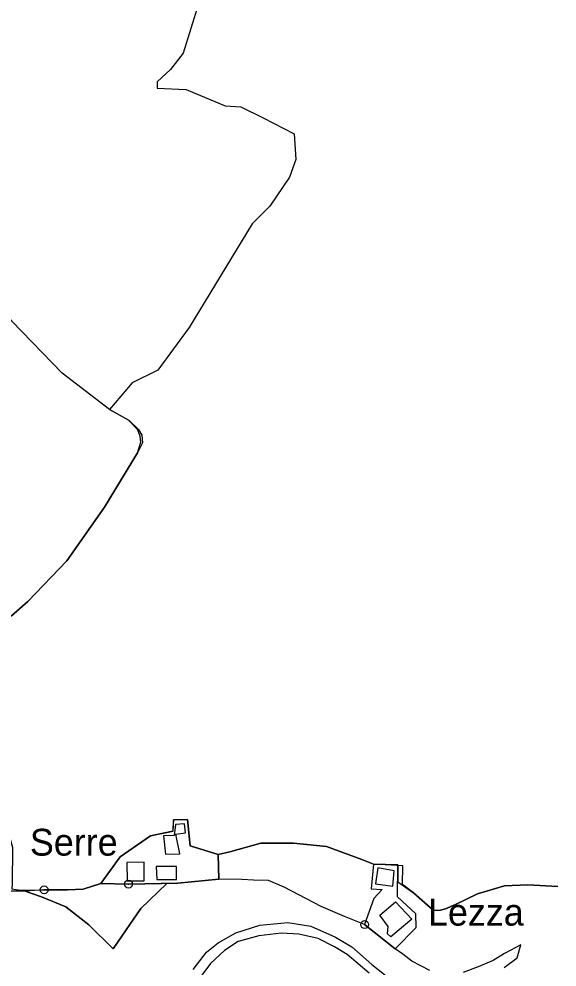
# Model space of a CAD drawing. Extents: x 645880 to 658994, y 884400 to 894744.
# Drawn here: x 656182 to 656523, y 891532 to 892132 of the extents above; entities that cross this region are included whole.
import ezdxf
from ezdxf.enums import TextEntityAlignment as Align

# ---------------------------------------------------------------- set-up
doc = ezdxf.new("R2010")
doc.units = 0
doc.header["$LTSCALE"] = 10
doc.header["$PDMODE"] = 32
doc.header["$PDSIZE"] = 5
for name, color, linetype, lineweight in [('16', 7, 'Continuous', 25), ('17', 7, 'Continuous', 25), ('18', 7, 'Continuous', 25), ('2', 7, 'Continuous', 25), ('55', 7, 'Continuous', 25)]:
    doc.layers.add(name, color=color, linetype=linetype, lineweight=lineweight)
doc.layers.add('60', color=7, linetype='Continuous')

msp = doc.modelspace()

# ---------------------------------------------------------------- linework, layer by layer
at = {"layer": '16'}
for points in [[(656342.45, 892161.69), (656338.47, 892159.67), (656332.55, 892160.05), (656325.48, 892161.2), (656314.98, 892164.64), (656305.18, 892167.58), (656295.98, 892141.92), (656286.31, 892110.77), (656278.25, 892100.48)], [(656278.25, 892100.48), (656269.75, 892092.5), (656269.93, 892088.54), (656288.2, 892087.79)], [(656288.2, 892087.79), (656312.86, 892077.43), (656322.84, 892076.67), (656336.96, 892069.7), (656356.54, 892059.72), (656357.68, 892043.32), (656353.74, 892032.14), (656341.25, 892013.72), (656330.08, 892002.53), (656290.11, 891936.91), (656270.32, 891909.76), (656254.02, 891901.9), (656239.58, 891884.9)], [(656239.58, 891884.9), (656251.8, 891878.19), (656258.02, 891872.19), (656260.02, 891868.63), (656260.47, 891863.74), (656257.36, 891857.51), (656236.47, 891823.03), (656212.68, 891789), (656187.83, 891763.23), (656177.5, 891754.21), (656170.25, 891748.49), (656160.57, 891743.21), (656154.2, 891735.29), (656153.25, 891723.59), (656156.3, 891713.28), (656159.36, 891704.5), (656162.03, 891693.05), (656165.84, 891680.45), (656167.75, 891672.44), (656167.75, 891657.93)], [(656167.75, 891657.93), (656167.75, 891649.15), (656170.42, 891639.61), (656174.23, 891627.77), (656175.38, 891617.47), (656178.1, 891607.41), (656178.04, 891584.27), (656177.78, 891581.2), (656183.34, 891580.26), (656198.23, 891580.51), (656212.94, 891580.51), (656222.91, 891580.94), (656234.08, 891584.44)], [(656234.09, 891584.44), (656246.39, 891601.53), (656265.52, 891614.69), (656279.87, 891617.77), (656280.21, 891624.95), (656289.09, 891625.12), (656290.7, 891608.37), (656308.39, 891602.9)], [(656308.39, 891602.9), (656315.93, 891604.71), (656335.61, 891610.04), (656356.28, 891610.04), (656377.18, 891607.94), (656399.51, 891599.77), (656406.94, 891596.73), (656422.4, 891596.41)], [(656422.4, 891596.41), (656422.23, 891585.59), (656432.3, 891578.53), (656444.62, 891567.63)], [(656444.62, 891567.63), (656447.38, 891567.41), (656449.23, 891567.57), (656452.44, 891568.46), (656458.87, 891571.22), (656472.84, 891578.01), (656489.88, 891582.98), (656504.64, 891583.68), (656523.56, 891582.71)]]:
    msp.add_lwpolyline(points, dxfattribs=at)
at = {"layer": '17'}
msp.add_line((656198.23, 891580.51), (656186.31, 891579.76), dxfattribs=at)
for points in [[(656177.5, 891754.21), (656187.83, 891763.23), (656212.68, 891789), (656236.47, 891823.03), (656257.36, 891857.51), (656259.4, 891864.17), (656259.02, 891868.12), (656257.33, 891872.27), (656251.68, 891878.11), (656239.58, 891884.9), (656209.68, 891907.91), (656177.72, 891940.91)], [(656251.69, 891584.17), (656234.08, 891584.44), (656222.91, 891580.94), (656212.94, 891580.51), (656198.23, 891580.51)], [(656275.98, 891584.56), (656259.46, 891568.7), (656250.27, 891555.09), (656242.05, 891543.13), (656226.49, 891558.32)], [(656226.49, 891558.32), (656242.05, 891543.13), (656250.27, 891555.09), (656259.46, 891568.7), (656275.98, 891584.56), (656272.24, 891584.5), (656251.69, 891584.17)], [(656401.27, 891558.49), (656388.45, 891563.53), (656373.75, 891569.91), (656359.54, 891577.26), (656350.23, 891582.17), (656340.43, 891586.34), (656330.87, 891586.58), (656323.52, 891587.07), (656308.89, 891587.35), (656282.99, 891584.67), (656275.98, 891584.56)], [(656186.31, 891579.75), (656168.2, 891579.6), (656168.12, 891556.06), (656168.45, 891532.73)], [(656186.31, 891579.76), (656196.53, 891575.99), (656211.96, 891569.69), (656226.49, 891558.32)], [(656226.49, 891558.32), (656211.96, 891569.69), (656196.53, 891575.99), (656186.32, 891579.75), (656186.31, 891579.75)], [(656292.61, 891530.02), (656301.19, 891541.01), (656308.4, 891546.85), (656319.73, 891553.38), (656334.84, 891558.19), (656352.7, 891559.91), (656367.12, 891557.5), (656382.91, 891550.63), (656393.22, 891544.45), (656405.92, 891533.11), (656418.97, 891522.8)], [(656404.21, 891527.62), (656390.13, 891539.65), (656382.23, 891544.46), (656371.93, 891549.61), (656359.57, 891552.36), (656348.58, 891553.04), (656334.16, 891551.33), (656321.11, 891547.89), (656312.53, 891542.05), (656303.6, 891533.81), (656287.8, 891512.5)], [(656442.51, 891529.38), (656431.26, 891535.26), (656425.45, 891539.75), (656420.54, 891543.12), (656401.27, 891558.49)], [(656489.57, 891531.26), (656497.95, 891537.46), (656500.12, 891545.63), (656489.78, 891540.14), (656482.63, 891535.67), (656473.18, 891531.71), (656463.61, 891528.13)]]:
    msp.add_lwpolyline(points, dxfattribs=at)
for p in [(656198.23, 891580.51), (656251.69, 891584.17), (656401.27, 891558.49)]:
    msp.add_point(p, dxfattribs=at)
at = {"layer": '18'}
for points in [[(656288.2, 892087.79), (656312.86, 892077.43), (656322.84, 892076.67), (656336.96, 892069.7), (656356.54, 892059.72), (656357.68, 892043.32), (656353.74, 892032.14), (656341.25, 892013.72), (656330.08, 892002.53), (656290.11, 891936.91), (656270.32, 891909.76), (656254.02, 891901.9), (656239.58, 891884.9), (656209.68, 891907.91), (656177.72, 891940.91), (656149.88, 891964.92), (656140.6, 891980.92), (656140.6, 892001.93), (656151.94, 892034.93), (656164.31, 892084.95), (656172.63, 892145.91)], [(656295.98, 892141.92), (656286.31, 892110.77), (656278.25, 892100.48)], [(656278.25, 892100.48), (656269.75, 892092.5), (656269.93, 892088.54), (656288.2, 892087.79)]]:
    msp.add_lwpolyline(points, dxfattribs=at)
at = {"layer": '2'}
for points in [[(656251.69, 891584.17), (656282.99, 891584.67), (656308.89, 891587.35), (656308.38, 891602.9), (656290.69, 891608.37), (656289.08, 891625.12), (656280.2, 891624.95), (656279.86, 891617.77), (656265.51, 891614.69), (656246.38, 891601.53), (656234.08, 891584.44)], [(656273.88, 891614.69), (656275.08, 891603.07), (656284.3, 891603.41), (656281.74, 891615.72), (656287.71, 891616.57), (656287.2, 891622.38), (656281.4, 891621.87), (656280.54, 891615.03)], [(656250.65, 891597.94), (656250.82, 891586.15), (656261.58, 891586.15), (656261.58, 891598.11)], [(656269.27, 891595.38), (656269.61, 891587.18), (656282.08, 891587.18), (656282.08, 891595.38)], [(656401.27, 891558.49), (656420.54, 891543.12), (656433.94, 891556.63), (656433.72, 891565.24), (656422.07, 891576.03), (656422.39, 891596.41), (656406.93, 891596.73), (656405.51, 891581.26), (656412.27, 891580.82), (656407.15, 891574.94)], [(656409.71, 891594.48), (656408.1, 891584.43), (656419.07, 891582.91), (656420, 891592.54)], [(656410.84, 891564.39), (656420.8, 891572.83), (656431.26, 891562.02), (656417.93, 891550.71), (656415.74, 891552.57), (656416.24, 891557.3)]]:
    msp.add_lwpolyline(points, close=True, dxfattribs=at)
at = {"layer": '55'}
msp.add_line((656444.62, 891567.62), (656432.3, 891578.53), dxfattribs=at)
for points in [[(656432.3, 891578.53), (656425.23, 891583.86), (656425.42, 891595.82), (656406.93, 891596.73), (656399.5, 891599.77), (656377.17, 891607.94), (656356.28, 891610.03), (656335.61, 891610.03), (656315.93, 891604.71), (656308.38, 891602.9)], [(656308.38, 891602.9), (656308.89, 891587.35), (656282.99, 891584.67), (656275.98, 891584.56), (656259.46, 891568.7), (656250.27, 891555.09), (656242.05, 891543.13), (656226.49, 891558.32), (656211.96, 891569.69), (656196.53, 891575.99), (656186.31, 891579.75), (656168.2, 891579.6)], [(656523.56, 891582.71), (656504.64, 891583.68), (656489.88, 891582.98), (656472.83, 891578.01), (656458.87, 891571.21), (656452.43, 891568.45), (656449.23, 891567.56), (656447.38, 891567.4), (656444.62, 891567.62)]]:
    msp.add_lwpolyline(points, dxfattribs=at)

# ---------------------------------------------------------------- texts
at = {"layer": '60'}
for s, p in [('Serre', (656217.01, 891602.2)), ('Lezza', (656471.72, 891557.85))]:
    msp.add_text(s, height=17, dxfattribs=at).set_placement(p, align=Align.CENTER)

doc.saveas('drawing.dxf')
